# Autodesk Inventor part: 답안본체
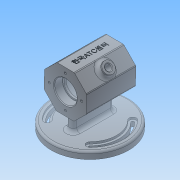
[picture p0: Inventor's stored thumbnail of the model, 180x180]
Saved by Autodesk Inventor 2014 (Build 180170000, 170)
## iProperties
Created: 2017-06
Part Number: 답안본체
Material: 일반
Document SubType Name: Modeling
Designer: NET
Density: 1 g/cm^3
Appearance: 기본값
Author: NET
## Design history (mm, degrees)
sketch "스케치1"
  geometry: C1 r 55 at (0, 0); 1 further point
  constraints: 1 centre point, 1 coincident
  dimensions: "d0" = 110 diameter of C1
extrude "돌출1" new body sketch "스케치1" distance "d1" = 10; taper "d2" = 0 deg
sketch "스케치2"
  geometry: L1 (0, 0)-(0, 62); L2 (0, 62)-(-35, 62); L3 (-35, 62)-(-35, 92); L4 (-35, 92)-(35, 92); L5 (35, 92)-(35, 62); L6 (35, 62)-(0, 62); L7 (-35, 62)-(-23, 62); L8 (-23, 62)-(-23, 77.7); L9 (-23.3, 78)-(-35, 78); L10 (0, 62)-(-20, 62); L11 (-20, 62)-(-20, 84); L12 (-17, 87)-(17, 87); L13 (20, 84)-(20, 62); L14 (35, 62)-(23, 62); L15 (23, 62)-(23, 77.7); L16 (23.3, 78)-(35, 78); L17 (23, 62)-(23, 76); L18 (23, 76)-(20, 76); L19 (-23, 62)-(-23, 76); L20 (-23, 76)-(-20, 76); A1 r 3 centre (-17, 84) between (-17, 87) and (-20, 84); A2 r 3 centre (17, 84) between (20, 84) and (17, 87); A3 r 0.3 centre (-23.3, 77.7) between (-23, 77.7) and (-23.3, 78); A4 r 0.3 centre (23.3, 77.7) between (23.3, 78) and (23, 77.7); 4 further points
  constraints: 40 end point, 18 point on line, 10 perpendicular, 8 point on circle, 8 tangent, 4 centre point, 4 parallel, 2 equal radius, 1 vertical
  dimensions: "d3" = 62 distance of L1.start L1.end; "d4" = 35 distance of L1.end L2.end; "d5" = 30 distance of L2.end L3.end; "d6" = 70 distance of L3.end L4.end; "d7" = 12 distance of L2.end L7.end; "d8" = 16 distance of L7.end point (-23, 78); "d9" = 20 distance of L1.end L10.end; "d10" = 25 distance of L10.end point (-20, 87); "d11" = 40 distance of point (-20, 87) point (20, 87); "d12" = 12 distance of L5.end L14.end; "d13" = 16 distance of L14.end point (23, 78); "d14" = 14 distance of L14.end L17.end; "d15" = 14 distance of L7.end L19.end; "d16" = 3 radius of A1; "d102" = 0.3 radius of A3
revolve "회전1" sketch "스케치2" stored, may be unused: angle "d17" = 90 deg
sketch "스케치3"
  geometry: L1 (0, 0)-(0, 50); L2 (0, 0)-(-16.273, 39.288); L3 (0, 30)-(-12.426, 30); L4 (17.179, 30.081)-(34.641, 0.163); L5 (34.641, 0.163)-(17.462, -29.918); L6 (17.462, -29.918)-(-17.179, -30.081); L7 (-17.179, -30.081)-(-34.641, -0.163); L8 (-34.641, -0.163)-(-17.462, 29.918); L9 (-17.462, 29.918)-(17.179, 30.081); 2 further points
  constraints: 18 end point, 2 point on line, 1 coincident, 1 horizontal, 1 perpendicular, 1 vertical, 1 vertical alignment, 14 other
  dimensions: "d18" = 50 distance of L1.start L1.end; "d19" = 22.5 deg angle of L1 L2; "d20" = 30 distance from line of L9 point (0, 0); "d21" = 17.17898 horizontal distance of L7.end L8.end
extrude "돌출2" join sketch "스케치3" distance "d22" = 70; taper "d23" = 0 deg
sketch "스케치5"
  geometry: L1 (0, 0)-(0, -24); L2 (0, 0)-(0, 24); L3 (-5, -24)-(-5, 24); L4 (5, -24)-(5, 24); C1 r 55 at (0, 0) reference; A1 r 5 centre (0, -24) between (-5, -24) and (5, -24); A2 r 5 centre (0, 24) between (-5, 24) and (5, 24)
  constraints: 8 end point, 4 point on circle, 2 centre point, 2 coincident, 2 equal length, 2 tangent, 1 vertical
  dimensions: "d58" = 24 distance of L1.start L1.end; "d59" = 10 diameter of A1; "d60" = 24 distance of L1.start L2.end; "d61" = 10 diameter of A2; "d62" = 10 distance between parallel lines of L4 L3
extrude "돌출4" join sketch "스케치5" stored distance "d63" = 10; taper "d64" = 0 deg
sketch "스케치6"
  geometry: L1 (30, -17.321)-(0, 0) reference; L2 (30, 51.962)-(60, 34.641) reference; L3 (45, 43.301)-(15, -8.66); L4 (0, 34.641)-(60, 0); C1 r 16 at (30, 17.321) reference; C2 r 2.5 at (41.5, 37.239); C3 r 2.5 at (10.081, 28.821); C4 r 2.5 at (18.5, -2.598); C5 r 2.5 at (49.919, 5.821); A1 r 23 centre (30, 17.321) between (41.5, 37.239) and (10.081, 28.821); 1 further point
  constraints: 5 centre point, 4 end point, 4 point on circle, 4 point on line, 2 midpoint, 1 coincident, 1 perpendicular
  dimensions: "d66" = 46 diameter of A1; "d67" = 5 diameter of C2; "d68" = 5 diameter of C3; "d69" = 5 diameter of C4; "d70" = 5 diameter of C5
hole "구멍1" sketch "스케치6" at (41.5, 37.239), (10.081, 28.821), (18.5, -2.598), (49.919, 5.821) diameter "d71" = 3.242; stored, may be unused: countersink angle "d75" = 90 deg, drill point angle "d77" = 118 deg; dims "d72" = 8, "d73" = 4, "d74" = 2, "d76" = 10
sketch "스케치7" dims "d78" = 46
  geometry: L1 (0, 0)-(30, -17.321) reference; L2 (60, 34.641)-(30, 51.962) reference; L3 (45, 43.301)-(15, -8.66); L4 (0, 34.641)-(60, 0); C1 r 16 at (30, 17.321) reference; C2 r 2 at (18.5, -2.598); C3 r 2 at (49.919, 5.821); C4 r 2 at (41.5, 37.239); C5 r 2 at (10.081, 28.821); 2 further points
  constraints: 4 centre point, 4 end point, 2 midpoint, 1 coincident, 1 perpendicular, 1 point on line, 12 other
  dimensions: "d79" = 4 diameter of C2; "d82" = 360 deg dimension on point (30, 17.321) C2.centre (derived)
hole "구멍2" sketch "스케치7" at (18.5, -2.598), (49.919, 5.821), (41.5, 37.239), (10.081, 28.821) diameter "d84" = 3.242; stored, may be unused: countersink angle "d88" = 90 deg, drill point angle "d90" = 118 deg; dims "d85" = 8, "d86" = 4, "d87" = 2, "d89" = 10
sketch "스케치8"
  geometry: L1 (0, 0)-(0, 70) reference; L2 (0, 0)-(0, 35); L3 (-17.321, 70)-(0, 70) reference; L4 (-17.321, 0)-(-17.321, 70) reference; L5 (-17.321, 0)-(0, 0) reference; L6 (0, 0)-(0, 70) reference; L7 (-17.321, 35)-(17.679, 35); 2 further points
  constraints: 4 end point, 2 midpoint, 1 coincident, 1 perpendicular, 1 other
  dimensions: "d91" = 35 distance of L1.start L2.end; "d92" = 35 distance of L7.start L7.end
feature "엠보싱1" sketch "스케치8" dims "d93" = 0.5, "d94" = 0
sketch "스케치11" dims "d117" = 4, "d118" = 4, "d119" = 4
  geometry: L1 (-5, -24)-(-5, 24) reference; L2 (-55, 0)-(55, 0); L3 (-26.87, 26.87)-(-45.953, 45.953); L4 (-26.87, -26.87)-(-33.941, -33.941); L5 (26.87, 26.87)-(33.941, 33.941); L6 (26.87, -26.87)-(33.941, -33.941); C1 r 48 at (0, 0); C2 r 5 at (-30.406, 30.406); A1 r 55 centre (0, 0) between (-55, 0) and (55, 0) reference; A2 r 5 centre (-30.406, -30.406) between (-33.941, -33.941) and (-26.87, -26.87); A3 r 5 centre (30.406, -30.406) between (26.87, -26.87) and (33.941, -33.941); A4 r 5 centre (30.406, 30.406) between (33.941, 33.941) and (26.87, 26.87); A5 r 2 centre (-30.406, -30.406) between (-28.991, -28.991) and (-28.959, -31.787); A6 r 38 centre (0, 0) between (26.87, -26.87) and (26.87, 26.87); A7 r 38 centre (0, 0) between (-26.87, 26.87) and (-26.87, -26.87); A8 r 41 centre (0, 0) between (28.991, -28.991) and (28.991, 28.991); A9 r 41 centre (0, 0) between (-28.991, 28.991) and (-28.991, -28.991); A10 r 43 centre (0, 0) between (28.959, -31.787) and (28.959, 31.787); A11 r 43 centre (0, 0) between (-28.959, 31.787) and (-28.959, -31.787); A12 r 45 centre (0, 0) between (31.82, -31.82) and (31.82, 31.82); A13 r 45 centre (0, 0) between (-31.82, 31.82) and (-31.82, -31.82); 4 further points
  constraints: 31 point on circle, 14 centre point, 10 coincident, 10 end point, 7 point on line, 3 midpoint, 1 perpendicular, 9 other
  dimensions: "d105" = 96 diameter of C1; "d106" = 110 distance of L2.start L2.end; "d108" = 10 diameter of A2; "d113" = 10 diameter of A3; "d115" = 10 diameter of A4; "d116" = 4 diameter of A5; "d122" = 19.08317 horizontal distance of L3.start L3.end; "d125" = 19.08317 horizontal distance of L3.start L3.end; "d127" = 38 radius of A6; "d128" = 41 radius of A8; "d129" = 43 radius of A10; "d130" = 45 radius of A12; "d131" = 38 radius of A7; "d132" = 41 radius of A9; "d133" = 43 radius of A11; "d134" = 45 radius of A13
extrude "돌출7" cut sketch "스케치11" stored distance "d135" = 7; taper "d136" = 0 deg
sketch "스케치12"
  geometry: L1 (-5, -24)-(-5, 24) reference; L2 (0, -55)-(0, 55); L3 (-55, 0)-(55, 0); L4 (28.991, -28.991)-(31.82, -31.82); L5 (28.991, 28.991)-(31.82, 31.82); A1 r 45 centre (0, 0) between (-31.82, 31.82) and (-31.82, -31.82) reference; A2 r 2 centre (-30.406, 30.406) between (-28.991, 28.991) and (-31.82, 31.82) reference; A3 r 2 centre (-30.406, -30.406) between (-31.82, -31.82) and (-28.991, -28.991) reference; A4 r 55 centre (0, 0) between (0, -55) and (0, 55) reference; A5 r 2 centre (30.406, -30.406) between (28.991, -28.991) and (31.82, -31.82); A6 r 2 centre (30.406, 30.406) between (31.82, 31.82) and (28.991, 28.991); A7 r 41 centre (0, 0) between (-28.991, 28.991) and (-28.991, -28.991); A8 r 41 centre (0, 0) between (28.991, -28.991) and (28.991, 28.991); A9 r 41 centre (0, 0) between (-28.991, 28.991) and (-28.991, -28.991); A10 r 45 centre (0, 0) between (31.82, -31.82) and (31.82, 31.82)
  constraints: 20 point on circle, 8 end point, 6 centre point, 2 coincident, 2 midpoint, 1 parallel, 1 perpendicular
  dimensions: "d137" = 110 distance of L2.start L2.end; "d141" = 4 diameter of A6; "d142" = 4 diameter of A5; "d143" = 110 distance of L3.start L3.end; "d144" = 30.40559 horizontal distance of A1.centre A5.centre; "d145" = 30.40559 distance from line of A6.centre L2; "d147" = 30.40559 distance from line of L3 A5.centre; "d148" = 41 radius of A8; "d149" = 45 radius of A10
extrude "돌출8" cut sketch "스케치12" stored distance "d150" = 7; taper "d151" = 0 deg
sketch "스케치13"
  geometry: C1 r 55 at (0, 0) reference; A1 r 45 centre (0, 0) between (31.82, -31.82) and (31.82, 31.82) reference; A2 r 2 centre (30.406, -30.406) between (28.991, -28.991) and (31.82, -31.82) reference; A3 r 41 centre (0, 0) between (28.991, -28.991) and (28.991, 28.991) reference; A4 r 2 centre (30.406, 30.406) between (31.82, 31.82) and (28.991, 28.991) reference; A5 r 2 centre (-30.406, 30.406) between (-28.991, 28.991) and (-31.82, 31.82) reference; A6 r 2 centre (-30.406, -30.406) between (-31.82, -31.82) and (-28.991, -28.991) reference; A7 r 5 centre (-30.406, -30.406) between (-26.87, -26.87) and (-33.941, -33.941); A8 r 5 centre (-30.406, 30.406) between (-26.87, 26.87) and (-33.941, 33.941); A9 r 5 centre (30.406, 30.406) between (26.87, 26.87) and (33.941, 33.941); A10 r 5 centre (30.406, -30.406) between (26.87, -26.87) and (33.941, -33.941); A11 r 38 centre (0, 0) between (26.87, -26.87) and (26.87, 26.87); A12 r 38 centre (0, 0) between (-26.87, 26.87) and (-26.87, -26.87); A13 r 48 centre (0, 0) between (33.941, -33.941) and (33.941, 33.941); A14 r 48 centre (0, 0) between (-33.941, 33.941) and (-33.941, -33.941)
  constraints: 16 point on circle, 8 centre point, 6 coincident
  dimensions: "d154" = 10 diameter of A7; "d155" = 10 diameter of A8; "d156" = 10 diameter of A9; "d157" = 10 diameter of A10; "d158" = 38 radius of A12; "d159" = 38 radius of A11; "d160" = 48 radius of A13; "d161" = 48 radius of A14
extrude "돌출9" cut sketch "스케치13" distance "d162" = 3; taper "d163" = 0 deg
chamfer "모따기1" distance "d164" = 1; stored, may be unused: second distance "d165" = 2, angle "d166" = 45 deg
chamfer "모따기2" distance "d167" = 1; stored, may be unused: second distance "d168" = 2, angle "d169" = 45 deg
fillet "모깎기1" dims "d170" = 1
fillet "모깎기2" dims "d171" = 3
fillet "모깎기3" dims "d172" = 5
sketch "스케치14"
  geometry: L1 (0, 0)-(0, 33.486) reference; L2 (29.5, -17.609)-(0.5, -0.866) reference; L3 (59.5, -0.866)-(30.5, -17.609) reference; L4 (60, 33.486)-(60, 0) reference; L5 (30.5, 51.095)-(59.5, 34.352) reference; L6 (0.5, 34.352)-(29.5, 51.095) reference; C1 r 17 at (30, 16.743) reference; C2 r 30 at (30, 16.743); A1 r 1 centre (1, 33.486) between (0.5, 34.352) and (0, 33.486) reference; A2 r 1 centre (1, 0) between (0, 0) and (0.5, -0.866) reference; A3 r 1 centre (30, -16.743) between (29.5, -17.609) and (30.5, -17.609) reference; A4 r 1 centre (59, 0) between (59.5, -0.866) and (60, 0) reference; A5 r 1 centre (59, 33.486) between (60, 33.486) and (59.5, 34.352) reference; A6 r 1 centre (30, 50.229) between (30.5, 51.095) and (29.5, 51.095) reference; 1 further point
  constraints: 1 centre point, 1 coincident
extrude "돌출10" cut sketch "스케치14" stored distance "d174" = 0; taper "d175" = 0 deg
sketch "스케치15"
  geometry: L1 (12.786, 29.848)-(30.147, 12.065); L2 (30.147, 12.065)-(29.848, -12.786); L3 (29.848, -12.786)-(12.065, -30.147); L4 (12.065, -30.147)-(-12.786, -29.848); L5 (-12.786, -29.848)-(-30.147, -12.065); L6 (-30.147, -12.065)-(-29.848, 12.786); L7 (-29.848, 12.786)-(-12.065, 30.147); L8 (-12.065, 30.147)-(12.786, 29.848); L9 (0, 0)-(-12.065, 30.147); L10 (0, 0)-(12.786, 29.848); C1 r 30 at (0, 0) reference; C2 r 17 at (0, 0) reference; 1 further point
  constraints: 20 end point, 1 coincident, 17 other
  dimensions: "d176" = 30 distance from line of L9.start L8; "d190" = 45 deg angle of L10 L9 (derived)
extrude "돌출11" join sketch "스케치15" distance "d177" = 70; taper "d178" = 0 deg
sketch "스케치16"
  geometry: L1 (0, 0)-(24.853, 0) reference; L2 (24.853, 0)-(24.853, 70) reference; L3 (12.426, 0)-(12.426, 35); C1 r 8 at (12.426, 35); 1 further point
  constraints: 2 end point, 1 centre point, 1 coincident, 1 midpoint, 1 parallel
  dimensions: "d180" = 35 distance of L3.start L3.end; "d181" = 16 diameter of C1
extrude "돌출12" join sketch "스케치16" distance "d182" = 7; taper "d183" = 0 deg
sketch "스케치17"
  geometry: C1 r 8 at (0, 0) reference; C2 r 4 at (0, 0); 1 further point
  constraints: 1 centre point, 1 coincident
  dimensions: "d184" = 8 diameter of C2
extrude "돌출13" cut sketch "스케치17" stored distance "d185" = 7; taper "d186" = 0 deg
fillet "모깎기5" dims "d187" = 5
fillet "모깎기6" dims "d188" = 2
fillet "모깎기7" dims "d189" = 2
chamfer "모따기3" distance "d191" = 1; stored, may be unused: second distance "d192" = 2, angle "d193" = 45 deg
node "솔리드1"
node "투영된 루프2"
other parameters: "d24" = 86, "d25" = 96, "d26" = 76, "d28" = 45 deg, "d29" = 45 deg, "d34" = 43, "d35" = 43, "d50" = 86, "d103" = 86, "d104" = 76, "d107" = 45 deg, "d109" = 45 deg, "d112" = 45 deg, "d114" = 45 deg, "d121" = 82, "d139" = 45 deg, "d140" = 45 deg, "d152" = 96, "d153" = 76
